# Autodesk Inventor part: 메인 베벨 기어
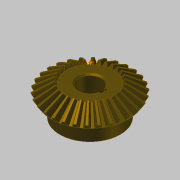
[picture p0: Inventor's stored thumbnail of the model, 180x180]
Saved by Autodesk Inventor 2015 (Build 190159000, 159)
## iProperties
Created: 2016-04
Part Number: 메인 베벨 기어
Material: 강철, 탄소
Document SubType Name: Modeling
Designer: mdu
Categories: <?xml version="1.0" encoding="UTF-16"?> <MemberInstance><Categories><FamilyTemplate><FamilyTemplateParameter ValueType="xs:double" Id="1" ObjectReferenceKey="da
Mass: 269.926 g
Surface Area: 108.837 cm^2
Volume: 34.2981 cm^3
Density: 7.87 g/cm^3
Appearance: 얼룩무늬
CustomPartVersion: 1
Author: mdu
Revision Number: 1
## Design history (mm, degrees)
node "맨 위 점"
node "메쉬 평면2"
sketch "톱니 본체 스케치"
  geometry: L1 (0, 0)-(28.669, -21.997); L2 (28.669, -21.997)-(31.109, -18.336); L3 (31.109, -18.336)-(0, 0); L4 (30, -20)-(0, 0); L5 (17.219, -13.212)-(18.685, -11.013); L6 (28.669, -21.997)-(17.219, -13.212); L7 (31.109, -18.336)-(18.685, -11.013); L8 (0, -39.387)-(0, 6.564) reference; L9 (0, -20)-(31.109, -20)
  constraints: 16 end point, 4 point on line, 3 perpendicular, 2 collinear, 1 horizontal alignment, 1 vertical alignment
  dimensions: "d0" = 60 diameter of L4.start L8 (= da_de); "d1" = 57.33744 diameter of L1.end L8 (= da_dfe); "d2" = 62.2188 diameter of L2.end L8 (= da_dae); "d3" = 14.4 distance between parallel lines of L2 L5 (= da_b); "d4" = 18.3359 vertical distance of L2.end L1.start (= da_ve)
revolve "톱니 본체" sketch "톱니 본체 스케치" stored, may be unused: angle "d5" = 90 deg
node "시작점"
node "톱니 평면"
sketch "시작 스케치"
  geometry: L1 (0, -23.505)-(0, 10.645) reference; L2 (-0.709, -2.928)-(0.709, -2.928); A1 r 19.188 centre (-19.457, -7.014) between (-0.709, -2.928) and (-3.232, 3.229); A2 r 19.188 centre (19.457, -7.014) between (3.232, 3.229) and (0.709, -2.928); A3 r 57.403 centre (0, -54.083) between (3.232, 3.229) and (-3.232, 3.229); 1 further point
  constraints: 6 point on circle, 3 centre point, 3 symmetric about line, 2 end point, 1 coincident, 1 perpendicular, 1 other
  dimensions: "d7" = 19.18795 radius of A1 (= fd_rr); "d8" = 19.45712 horizontal distance of point (0, -54.083) A1.centre (= fd_x); "d9" = 47.06905 vertical distance of point (0, -54.083) A1.centre (= fd_y); "d57" = 57.40327 radius of A3 (= 0.5 x fd_dva + 0.3 x da_he); "d58" = 51.15527 distance from line of A3.centre L2 (= 0.5 x fd_dva - 1.12 x da_he)
node "끝점"
  node "끝 평면"
sketch "3D 스케치 오른쪽"
  node "Helical Curve Right" dims "d65" = 229.90621 (computed from da_dm, da_delta, da_beta), "d66" = 31.5, "d67" = 60 (= da_de), "d68" = -9.82794 (= -da_delta), "d69" = 8.10972 (computed from fd_loft, da_delta)
node "끝 평면 오른쪽"
sketch "끝 스케치 오른쪽"
  geometry: L1 (0, -41.54)-(0, 13.178) reference; L2 (-0.422, -1.69)-(0.422, -1.69); A1 r 11.427 centre (-11.587, -4.123) between (-0.422, -1.69) and (-1.925, 1.977); A2 r 11.427 centre (11.587, -4.123) between (1.925, 1.977) and (0.422, -1.69); A3 r 34.184 centre (0, -32.153) between (1.925, 1.977) and (-1.925, 1.977); 1 further point
  constraints: 6 point on circle, 3 centre point, 3 symmetric about line, 2 end point, 1 coincident, 1 perpendicular, 1 other
  dimensions: "d70" = 11.58699 horizontal distance of A3.centre A1.centre (computed from fd_x, fd_ratio); "d71" = 28.03028 vertical distance of point (0, -32.153) A1.centre (computed from fd_y, fd_ratio); "d72" = 11.4267 radius of A1 (computed from fd_rr, fd_ratio); "d73" = 30.46369 distance from line of point (0, -32.153) L2 (computed from d58, fd_ratio); "d74" = 34.18446 radius of A3 (computed from d57, fd_ratio)
feature "로프트 오른쪽" sketch "끝 스케치 오른쪽" dims "d75" = 0, "d77" = 0, "d79" = 0, "d80" = 90 deg, "d85" = 20, "d92" = 90 deg, "d93" = 90 deg, "da_teethtype" = 0 [user parameter]
sketch "3D 스케치 왼쪽"
  node "Helical Curve Left" dims "d26" = 229.90621 (computed from da_dm, da_delta, da_beta), "d27" = 8.10972 (computed from fd_loft, da_delta), "d28" = 60 (= da_de), "d29" = -9.82794 (= -da_delta)
node "끝 평면 왼쪽"
sketch "끝 스케치 왼쪽" dims "d56" = 10.3728 (derived)
  geometry: L1 (0, -43.753)-(0, 15.405) reference; L2 (-0.422, -1.678)-(0.422, -1.678); A1 r 11.427 centre (-11.587, -4.111) between (-0.422, -1.678) and (-1.925, 1.988); A2 r 11.427 centre (11.587, -4.111) between (1.925, 1.988) and (0.422, -1.678); A3 r 34.184 centre (0, -32.142) between (1.925, 1.988) and (-1.925, 1.988); 2 further points; 1 other entity
  constraints: 6 point on circle, 3 centre point, 3 symmetric about line, 2 end point, 1 coincident, 2 other
  dimensions: "d30" = 11.4267 radius of A1 (computed from fd_rr, fd_ratio); "d31" = 11.58699 horizontal distance of point (0, -32.142) A1.centre (computed from fd_x, fd_ratio); "d32" = 28.03028 vertical distance of A1.centre point (0, -32.142) (computed from fd_y, fd_ratio); "d61" = 34.18446 radius of A3 (computed from d57, fd_ratio); "d62" = 30.46369 distance from line of point (0, -32.142) L2 (computed from d58, fd_ratio)
feature "로프트 왼쪽" sketch "끝 스케치 왼쪽" dims "d35" = 0, "d37" = 0, "d39" = 0, "d40" = 90 deg, "d84" = 10, "d90" = 90 deg, "d91" = 90 deg, "da_teethtype" = 0 [user parameter]
sketch "본체 스케치"
  geometry: L1 (0, -35.038)-(0, -19.531) reference; L2 (28.669, -21.997)-(17.219, -13.212) reference; L3 (17.219, -13.212)-(0, -13.212); L4 (28.669, -21.997)-(0, -21.997)
  constraints: 4 end point, 2 perpendicular, 2 point on line
revolve "본체 고정" sketch "본체 스케치" stored, may be unused: angle "d46" = 90 deg
feature "피치 지름" dims angle "d47" = 90 deg
sketch "스케치8"
  geometry: C1 r 22.5 at (0, 0); 1 further point
  constraints: 1 centre point, 1 coincident
  dimensions: "d94" = 45 diameter of C1
extrude "돌출1" join sketch "스케치8" distance "d95" = 13; taper "d96" = 0 deg
sketch "스케치9"
  geometry: 1 further point
hole "구멍1" sketch "스케치9" at (0, 0) diameter "d97" = 17; stored, may be unused: countersink angle "d101" = 90 deg, drill point angle "d103" = 118 deg; dims "d98" = 6, "d99" = 4, "d100" = 2, "d102" = 8
sketch "스케치10"
  geometry: L1 (8.124, 2.5)-(10.8, 2.5); L2 (10.8, 2.5)-(10.8, -2.5); L3 (10.8, -2.5)-(8.124, -2.5); A1 r 8.5 centre (0, 0) between (8.124, 2.5) and (8.124, -2.5) reference; 1 further point
  constraints: 6 end point, 2 parallel, 2 point on circle, 1 horizontal, 1 perpendicular
  dimensions: "d104" = 5 distance of L1.end L2.end; "d112" = 19.3 dimension on A1 L2
extrude "돌출2" cut sketch "스케치10" stored distance "d106" = 10; taper "d107" = 0 deg
chamfer "모따기1" distance "d108" = 1; stored, may be unused: second distance "d109" = 2, angle "d110" = 45 deg
fillet "모깎기1" dims "d111" = 2
body "Solid1"
feature "로프트" dims "d17" = 0, "d18" = 90 deg, "d19" = 0, "d20" = 90 deg, "d89" = 0, "da_teethtype" = 0 [user parameter]
pattern_circular "원형 패턴" dims angle "d22" = 360 deg, "d88" = 0, "da_teethtype" = 0 [user parameter]
pattern_circular "원형 패턴 오른쪽" dims angle "d82" = 360 deg, "da_teethtype" = 0 [user parameter]
pattern_circular "원형 패턴 왼쪽" dims angle "d42" = 360 deg, "da_teethtype" = 0 [user parameter]
sketch "끝 스케치"
  geometry: L1 (0, -15.359)-(0, 6.983) reference; L2 (-0.422, -1.69)-(0.422, -1.69); A1 r 11.427 centre (-11.587, -4.123) between (-0.422, -1.69) and (-1.925, 1.977); A2 r 11.427 centre (11.587, -4.123) between (1.925, 1.977) and (0.422, -1.69); A3 r 34.184 centre (0, -32.153) between (1.925, 1.977) and (-1.925, 1.977); 1 further point
  constraints: 6 point on circle, 3 centre point, 3 symmetric about line, 2 end point, 1 coincident, 1 other
  dimensions: "d12" = 11.4267 radius of A1 (computed from fd_rr, fd_ratio); "d15" = 11.58699 horizontal distance of A1.centre point (0, -32.153) (computed from fd_x, fd_ratio); "d16" = 28.03028 vertical distance of A1.centre point (0, -32.153) (computed from fd_y, fd_ratio); "d59" = 34.18446 radius of A3 (computed from d57, fd_ratio); "d60" = 30.46369 distance from line of A3.centre L2 (computed from d58, fd_ratio)
sketch "Sketch6"
  geometry: L1 (30, -20)-(0, 0) reference; L2 (0, -37.8)-(0, 6.3) reference
body "Srf1"
other parameters: "da_b" = 14.4 [user parameter; used in 2 equation terms], "da_de" = 60 [user parameter; used in 4 equation terms], "da_dae" = 62.2188 [user parameter; used in 2 equation terms], "da_dfe" = 57.33744 [user parameter; used in 1 equation term], "da_le" = 36.05551 [user parameter; used in 1 equation term], "da_omega" = 90 deg [user parameter; used in 1 equation term], "da_beta" = 0 [user parameter; used in 2 equation terms], "da_delta" = 9.82794 [user parameter; used in 8 equation terms], "da_alpha" = 20 deg [user parameter; used in 2 equation terms], "da_he" = 4.4 [user parameter; used in 4 equation terms], "da_ve" = 18.3359 [user parameter; used in 1 equation term], "fd_dv" = 108.16654 (computed from da_de, da_delta) [user parameter; used in 1 equation term], "fd_dva" = 112.16654 (computed from da_dae, da_delta) [user parameter; used in 3 equation terms], "fd_dvb" = 101.6433 (computed from fd_dv, da_alpha) [user parameter; used in 2 equation terms], "da_zv" = 540.83269 [user parameter; used in 1 equation term], "fd_loft" = 14.62 (= da_b + 0.05 x da_he) [user parameter; used in 4 equation terms], "fd_ratio" = 5.95514 (computed from da_le, fd_loft) [user parameter; used in 15 equation terms], "fd_rr" = 19.18795 (computed from fd_dd, fd_dvb) [user parameter; used in 6 equation terms], "fd_angle" = 0.29367 (computed from da_zv) [user parameter; used in 4 equation terms], "fd_x1" = 1.58802 (computed from da_dvw, fd_angle) [user parameter; used in 1 equation term], "fd_y1" = 54.05995 (computed from da_dvw, fd_angle) [user parameter; used in 1 equation term], "fd_x2" = 17.8691 (computed from fd_rr, fd_angle2, fd_angle) [user parameter; used in 1 equation term], "fd_y2" = 6.9909 (computed from fd_rr, fd_angle2, fd_angle) [user parameter; used in 1 equation term], "fd_x" = 19.45712 (= fd_x1 + fd_x2) [user parameter; used in 4 equation terms], "fd_y" = 47.06905 (= fd_y1 - fd_y2) [user parameter; used in 4 equation terms], "fd_angle2" = 3.43555 (computed from fd_dvb, fd_dd, da_alpha) [user parameter; used in 2 equation terms], "fd_dd" = 108.64654 (= fd_dva - 0.8 x da_he) [user parameter; used in 2 equation terms], "da_dvw" = 108.16654 [user parameter; used in 2 equation terms], "d11" = 14.62 (= fd_loft), "da_dm" = 48.01848 [user parameter; used in 2 equation terms], "da_x" = 0 [user parameter], "da_m" = 2 [user parameter], "d48" = 0, "d49" = 0, "d50" = 90 deg (= da_omega), "d51" = 6 deg (computed from da_z), "d52" = 0, "d53" = 0, "d54" = 0
